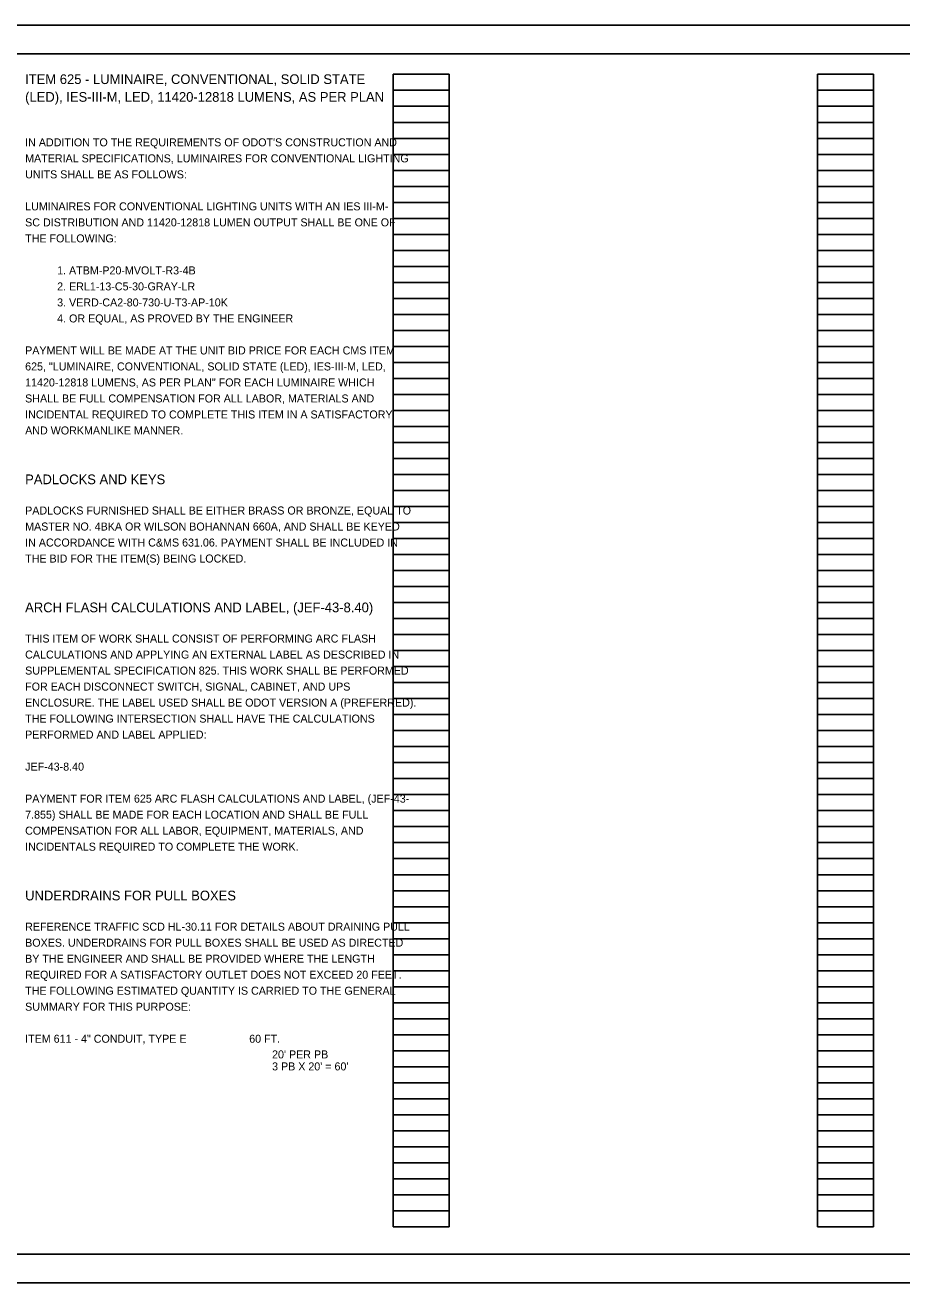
# Model space of a CAD drawing. Extents: x 0 to 49.8, y 0 to 22.
# Drawn here: x 9.82 to 25.16, y 0 to 22 of the extents above; entities that cross this region are included whole.
import ezdxf

# ---------------------------------------------------------------- set-up
doc = ezdxf.new("R2010")
doc.units = 0
for name, color, linetype in [('SC_Scratch1', 7, 'Continuous'), ('SH_Border', 7, 'Continuous'), ('SH_Cut_Line', 7, 'Continuous'), ('SH_Data', 7, 'Continuous'), ('SH_Text', 7, 'Continuous')]:
    doc.layers.add(name, color=color, linetype=linetype)

msp = doc.modelspace()

# ---------------------------------------------------------------- linework, layer by layer
at = {"layer": 'SH_Border'}
msp.add_lwpolyline([(1.5, 21.5), (33.5, 21.5), (33.5, 0.5), (1.5, 0.5)], close=True, dxfattribs=at)
at = {"layer": 'SH_Cut_Line'}
msp.add_lwpolyline([(0, 0), (34, 0), (34, 22), (0, 22)], close=True, dxfattribs=at)
at = {"layer": 'SH_Data'}
for p, q in [((16.26, 0.98), (16.26, 21.14)), ((16.26, 21.14), (17.24, 21.14)), ((17.24, 0.98), (17.24, 21.14)), ((23.68, 0.98), (23.68, 21.14)), ((23.68, 21.14), (24.66, 21.14)), ((24.66, 0.98), (24.66, 21.14)), ((16.26, 20.86), (17.24, 20.86)), ((23.68, 20.86), (24.66, 20.86)), ((16.26, 20.58), (17.24, 20.58)), ((23.68, 20.58), (24.66, 20.58)), ((16.26, 20.3), (17.24, 20.3)), ((23.68, 20.3), (24.66, 20.3)), ((16.26, 20.02), (17.24, 20.02)), ((23.68, 20.02), (24.66, 20.02)), ((16.26, 19.74), (17.24, 19.74)), ((23.68, 19.74), (24.66, 19.74)), ((16.26, 19.46), (17.24, 19.46)), ((23.68, 19.46), (24.66, 19.46)), ((16.26, 19.18), (17.24, 19.18)), ((23.68, 19.18), (24.66, 19.18)), ((16.26, 18.9), (17.24, 18.9)), ((23.68, 18.9), (24.66, 18.9)), ((16.26, 18.62), (17.24, 18.62)), ((23.68, 18.62), (24.66, 18.62)), ((16.26, 18.34), (17.24, 18.34)), ((23.68, 18.34), (24.66, 18.34)), ((16.26, 18.06), (17.24, 18.06)), ((23.68, 18.06), (24.66, 18.06)), ((16.26, 17.78), (17.24, 17.78)), ((23.68, 17.78), (24.66, 17.78)), ((16.26, 17.5), (17.24, 17.5)), ((23.68, 17.5), (24.66, 17.5)), ((16.26, 17.22), (17.24, 17.22)), ((23.68, 17.22), (24.66, 17.22)), ((16.26, 16.94), (17.24, 16.94)), ((23.68, 16.94), (24.66, 16.94)), ((16.26, 16.66), (17.24, 16.66)), ((23.68, 16.66), (24.66, 16.66)), ((16.26, 16.38), (17.24, 16.38)), ((23.68, 16.38), (24.66, 16.38)), ((16.26, 16.1), (17.24, 16.1)), ((23.68, 16.1), (24.66, 16.1)), ((16.26, 15.82), (17.24, 15.82)), ((23.68, 15.82), (24.66, 15.82)), ((16.26, 15.54), (17.24, 15.54)), ((23.68, 15.54), (24.66, 15.54)), ((16.26, 15.26), (17.24, 15.26)), ((23.68, 15.26), (24.66, 15.26)), ((16.26, 14.98), (17.24, 14.98)), ((23.68, 14.98), (24.66, 14.98)), ((16.26, 14.7), (17.24, 14.7)), ((23.68, 14.7), (24.66, 14.7)), ((16.26, 14.42), (17.24, 14.42)), ((23.68, 14.42), (24.66, 14.42)), ((16.26, 14.14), (17.24, 14.14)), ((23.68, 14.14), (24.66, 14.14)), ((16.26, 13.86), (17.24, 13.86)), ((23.68, 13.86), (24.66, 13.86)), ((16.26, 13.58), (17.24, 13.58)), ((23.68, 13.58), (24.66, 13.58)), ((16.26, 13.3), (17.24, 13.3)), ((23.68, 13.3), (24.66, 13.3)), ((16.26, 13.02), (17.24, 13.02)), ((23.68, 13.02), (24.66, 13.02)), ((16.26, 12.74), (17.24, 12.74)), ((23.68, 12.74), (24.66, 12.74)), ((16.26, 12.46), (17.24, 12.46)), ((23.68, 12.46), (24.66, 12.46)), ((16.26, 12.18), (17.24, 12.18)), ((23.68, 12.18), (24.66, 12.18)), ((16.26, 11.9), (17.24, 11.9)), ((23.68, 11.9), (24.66, 11.9)), ((16.26, 11.62), (17.24, 11.62)), ((23.68, 11.62), (24.66, 11.62)), ((16.26, 11.34), (17.24, 11.34)), ((23.68, 11.34), (24.66, 11.34)), ((16.26, 11.06), (17.24, 11.06)), ((23.68, 11.06), (24.66, 11.06)), ((16.26, 10.78), (17.24, 10.78)), ((23.68, 10.78), (24.66, 10.78)), ((16.26, 10.5), (17.24, 10.5)), ((23.68, 10.5), (24.66, 10.5)), ((16.26, 10.22), (17.24, 10.22)), ((23.68, 10.22), (24.66, 10.22)), ((16.26, 9.94), (17.24, 9.94)), ((23.68, 9.94), (24.66, 9.94)), ((16.26, 9.66), (17.24, 9.66)), ((23.68, 9.66), (24.66, 9.66)), ((16.26, 9.38), (17.24, 9.38)), ((23.68, 9.38), (24.66, 9.38)), ((16.26, 9.1), (17.24, 9.1)), ((23.68, 9.1), (24.66, 9.1)), ((16.26, 8.82), (17.24, 8.82)), ((23.68, 8.82), (24.66, 8.82)), ((16.26, 8.54), (17.24, 8.54)), ((23.68, 8.54), (24.66, 8.54)), ((16.26, 8.26), (17.24, 8.26)), ((23.68, 8.26), (24.66, 8.26)), ((16.26, 7.98), (17.24, 7.98)), ((23.68, 7.98), (24.66, 7.98)), ((16.26, 7.7), (17.24, 7.7)), ((23.68, 7.7), (24.66, 7.7)), ((16.26, 7.42), (17.24, 7.42)), ((23.68, 7.42), (24.66, 7.42)), ((16.26, 7.14), (17.24, 7.14)), ((23.68, 7.14), (24.66, 7.14)), ((16.26, 6.86), (17.24, 6.86)), ((23.68, 6.86), (24.66, 6.86)), ((16.26, 6.58), (17.24, 6.58)), ((23.68, 6.58), (24.66, 6.58)), ((16.26, 6.3), (17.24, 6.3)), ((23.68, 6.3), (24.66, 6.3)), ((16.26, 6.02), (17.24, 6.02)), ((23.68, 6.02), (24.66, 6.02)), ((16.26, 5.74), (17.24, 5.74)), ((23.68, 5.74), (24.66, 5.74)), ((16.26, 5.46), (17.24, 5.46)), ((23.68, 5.46), (24.66, 5.46)), ((16.26, 5.18), (17.24, 5.18)), ((23.68, 5.18), (24.66, 5.18)), ((16.26, 4.9), (17.24, 4.9)), ((23.68, 4.9), (24.66, 4.9)), ((16.26, 4.62), (17.24, 4.62)), ((23.68, 4.62), (24.66, 4.62)), ((16.26, 4.34), (17.24, 4.34)), ((23.68, 4.34), (24.66, 4.34)), ((16.26, 4.06), (17.24, 4.06)), ((23.68, 4.06), (24.66, 4.06)), ((16.26, 3.78), (17.24, 3.78)), ((23.68, 3.78), (24.66, 3.78)), ((16.26, 3.5), (17.24, 3.5)), ((23.68, 3.5), (24.66, 3.5)), ((16.26, 3.22), (17.24, 3.22)), ((23.68, 3.22), (24.66, 3.22)), ((16.26, 2.94), (17.24, 2.94)), ((23.68, 2.94), (24.66, 2.94)), ((16.26, 2.66), (17.24, 2.66)), ((23.68, 2.66), (24.66, 2.66)), ((16.26, 2.38), (17.24, 2.38)), ((23.68, 2.38), (24.66, 2.38)), ((16.26, 2.1), (17.24, 2.1)), ((23.68, 2.1), (24.66, 2.1)), ((16.26, 1.82), (17.24, 1.82)), ((23.68, 1.82), (24.66, 1.82)), ((16.26, 1.54), (17.24, 1.54)), ((23.68, 1.54), (24.66, 1.54)), ((16.26, 1.26), (17.24, 1.26)), ((23.68, 1.26), (24.66, 1.26)), ((16.26, 0.98), (17.24, 0.98)), ((23.68, 0.98), (24.66, 0.98))]:
    msp.add_line(p, q, dxfattribs=at)

# ---------------------------------------------------------------- texts
at = {"layer": 'SC_Scratch1'}
for s, p in [("20' PER PB ", (14.14, 3.926)), ("3 PB X 20' = 60'", (14.14, 3.716))]:
    msp.add_text(s, height=0.14, dxfattribs=at).set_placement(p)
at = {"layer": 'SH_Text'}
for s, height, p in [('ITEM 625 - LUMINAIRE, CONVENTIONAL, SOLID STATE ', 0.17, (9.82, 20.97)), ('(LED), IES-III-M, LED, 11420-12818 LUMENS, AS PER PLAN', 0.17, (9.82, 20.66)), ("IN ADDITION TO THE REQUIREMENTS OF ODOT'S CONSTRUCTION AND ", 0.14, (9.82, 19.88)), ('MATERIAL SPECIFICATIONS, LUMINAIRES FOR CONVENTIONAL LIGHTING ', 0.14, (9.82, 19.6)), ('UNITS SHALL BE AS FOLLOWS:', 0.14, (9.82, 19.32)), ('LUMINAIRES FOR CONVENTIONAL LIGHTING UNITS WITH AN IES III-M-', 0.14, (9.82, 18.76)), ('SC DISTRIBUTION AND 11420-12818 LUMEN OUTPUT SHALL BE ONE OF ', 0.14, (9.82, 18.48)), ('THE FOLLOWING:', 0.14, (9.82, 18.2)), ('1. ATBM-P20-MVOLT-R3-4B', 0.14, (10.38, 17.64)), ('2. ERL1-13-C5-30-GRAY-LR', 0.14, (10.38, 17.36)), ('3. VERD-CA2-80-730-U-T3-AP-10K', 0.14, (10.38, 17.08)), ('4. OR EQUAL, AS PROVED BY THE ENGINEER', 0.14, (10.38, 16.8)), ('PAYMENT WILL BE MADE AT THE UNIT BID PRICE FOR EACH CMS ITEM ', 0.14, (9.82, 16.24)), ('625, "LUMINAIRE, CONVENTIONAL, SOLID STATE (LED), IES-III-M, LED, ', 0.14, (9.82, 15.96)), ('11420-12818 LUMENS, AS PER PLAN" FOR EACH LUMINAIRE WHICH ', 0.14, (9.82, 15.68)), ('SHALL BE FULL COMPENSATION FOR ALL LABOR, MATERIALS AND ', 0.14, (9.82, 15.4)), ('INCIDENTAL REQUIRED TO COMPLETE THIS ITEM IN A SATISFACTORY ', 0.14, (9.82, 15.12)), ('AND WORKMANLIKE MANNER. ', 0.14, (9.82, 14.84)), ('PADLOCKS AND KEYS', 0.17, (9.82, 13.97)), ('PADLOCKS FURNISHED SHALL BE EITHER BRASS OR BRONZE, EQUAL TO ', 0.14, (9.82, 13.44)), ('MASTER NO. 4BKA OR WILSON BOHANNAN 660A, AND SHALL BE KEYED ', 0.14, (9.82, 13.16)), ('IN ACCORDANCE WITH C&MS 631.06. PAYMENT SHALL BE INCLUDED IN ', 0.14, (9.82, 12.88)), ('THE BID FOR THE ITEM(S) BEING LOCKED.', 0.14, (9.82, 12.6)), ('ARCH FLASH CALCULATIONS AND LABEL, (JEF-43-8.40)', 0.17, (9.82, 11.73)), ('THIS ITEM OF WORK SHALL CONSIST OF PERFORMING ARC FLASH ', 0.14, (9.82, 11.2)), ('CALCULATIONS AND APPLYING AN EXTERNAL LABEL AS DESCRIBED IN ', 0.14, (9.82, 10.92)), ('SUPPLEMENTAL SPECIFICATION 825. THIS WORK SHALL BE PERFORMED ', 0.14, (9.82, 10.64)), ('FOR EACH DISCONNECT SWITCH, SIGNAL, CABINET, AND UPS ', 0.14, (9.82, 10.36)), ('ENCLOSURE. THE LABEL USED SHALL BE ODOT VERSION A (PREFERRED). ', 0.14, (9.82, 10.08)), ('THE FOLLOWING INTERSECTION SHALL HAVE THE CALCULATIONS ', 0.14, (9.82, 9.8)), ('PERFORMED AND LABEL APPLIED:', 0.14, (9.82, 9.52)), ('JEF-43-8.40', 0.14, (9.82, 8.96)), ('PAYMENT FOR ITEM 625 ARC FLASH CALCULATIONS AND LABEL, (JEF-43-', 0.14, (9.82, 8.4)), ('7.855) SHALL BE MADE FOR EACH LOCATION AND SHALL BE FULL ', 0.14, (9.82, 8.12)), ('COMPENSATION FOR ALL LABOR, EQUIPMENT, MATERIALS, AND ', 0.14, (9.82, 7.84)), ('INCIDENTALS REQUIRED TO COMPLETE THE WORK.', 0.14, (9.82, 7.56)), ('UNDERDRAINS FOR PULL BOXES', 0.17, (9.82, 6.69)), ('REFERENCE TRAFFIC SCD HL-30.11 FOR DETAILS ABOUT DRAINING PULL ', 0.14, (9.82, 6.16)), ('BOXES. UNDERDRAINS FOR PULL BOXES SHALL BE USED AS DIRECTED ', 0.14, (9.82, 5.88)), ('BY THE ENGINEER AND SHALL BE PROVIDED WHERE THE LENGTH ', 0.14, (9.82, 5.6)), ('REQUIRED FOR A SATISFACTORY OUTLET DOES NOT EXCEED 20 FEET. ', 0.14, (9.82, 5.32)), ('THE FOLLOWING ESTIMATED QUANTITY IS CARRIED TO THE GENERAL ', 0.14, (9.82, 5.04)), ('SUMMARY FOR THIS PURPOSE:', 0.14, (9.82, 4.76)), ('ITEM 611 - 4" CONDUIT, TYPE E', 0.14, (9.82, 4.2)), ('60 FT.', 0.14, (13.74, 4.2))]:
    msp.add_text(s, height=height, dxfattribs=at).set_placement(p)

doc.saveas('drawing.dxf')
